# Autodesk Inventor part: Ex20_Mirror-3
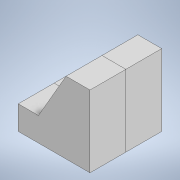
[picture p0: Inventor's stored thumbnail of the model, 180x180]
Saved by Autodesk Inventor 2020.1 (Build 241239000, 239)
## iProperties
Created: 2019-11
Part Number: Ex20_Mirror-3
Material: Generic
Document SubType Name: Modeling
Designer: Synergysoft Dell02
Density: 1 g/cm^3
Appearance: Default
Author: Synergysoft Dell02
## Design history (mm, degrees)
sketch "Sketch1"
  geometry: L1 (0, 30)-(-10, 30); L2 (-10, 30)-(-21.547, 10); L3 (-21.547, 10)-(-30, 10); L4 (-30, 10)-(-30, 0); L5 (-30, 0)-(0, 0); L6 (0, 0)-(0, 30)
  constraints: 12 end point, 3 perpendicular, 1 horizontal, 1 parallel
  dimensions: "d0" = 10 distance between parallel lines of L5 L3; "d1" = 30 deg angle of L6 L2; "d2" = 30 distance of L5.end L1.start; "d3" = 30 distance between parallel lines of L6 L4; "d4" = 10 distance of L1.start L1.end
extrude "Extrusion1" new body sketch "Sketch1" distance "d5" = 15; taper "d6" = 0 deg
mirror "Mirror1"
body "Solid1"
feature "Pattern of Solid1:1"
body "Solid2"
